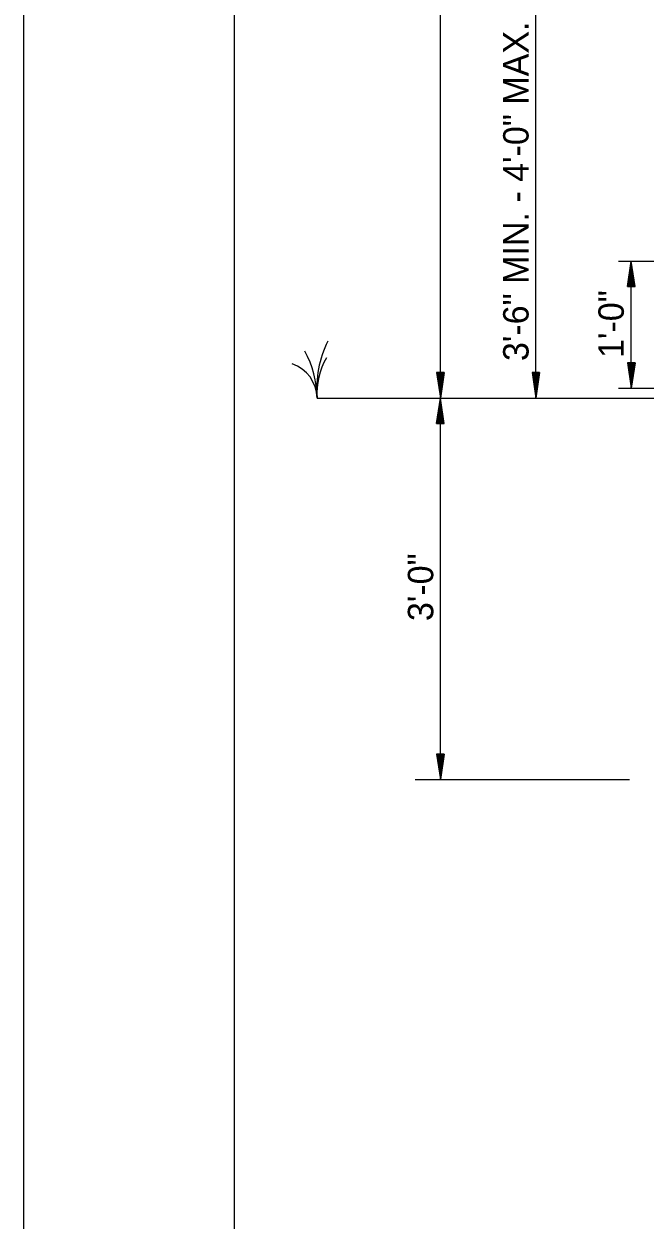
# Model space of a CAD drawing. Extents: x 1369885 to 1370886, y 379976 to 380616.
# Drawn here: x 1369885.5 to 1369995.4, y 380298 to 380509.6 of the extents above; entities that cross this region are included whole.
import ezdxf

# ---------------------------------------------------------------- set-up
doc = ezdxf.new("R2010")
doc.units = 0
for name, color, linetype in [('R_Border', 7, 'Continuous'), ('R_Draft', 7, 'Continuous'), ('R_No Plot', 7, 'Continuous')]:
    doc.layers.add(name, color=color, linetype=linetype)

msp = doc.modelspace()

# ---------------------------------------------------------------- linework, layer by layer
at = {"layer": 'R_Border'}
msp.add_line((1369922.71, 379987.52), (1369922.71, 380603.9), dxfattribs=at)
at = {"layer": 'R_Draft'}
for p, q in [((1369959.17, 380443.41), (1369959.17, 380582)), ((1369976.05, 380443.41), (1369976.05, 380533.41)), ((1369990.67, 380467.63), (1370003.78, 380467.63)), ((1369992.25, 380463.13), (1369992.92, 380467.63)), ((1369992.92, 380445.13), (1369992.92, 380467.63)), ((1369993.6, 380463.13), (1369992.92, 380467.63)), ((1369992.36, 380463.13), (1369992.92, 380466.88)), ((1369992.48, 380463.13), (1369992.92, 380466.1)), ((1369992.59, 380463.13), (1369992.92, 380465.35)), ((1369993.49, 380463.13), (1369992.92, 380466.88)), ((1369993.37, 380463.13), (1369992.92, 380466.1)), ((1369993.26, 380463.13), (1369992.92, 380465.35)), ((1369992.25, 380463.13), (1369993.6, 380463.13)), ((1369992.7, 380463.13), (1369992.92, 380464.59)), ((1369992.82, 380463.13), (1369992.92, 380463.84)), ((1369993.14, 380463.13), (1369992.92, 380464.59)), ((1369993.03, 380463.13), (1369992.92, 380463.84)), ((1369992.25, 380449.63), (1369992.92, 380445.13)), ((1369993.6, 380449.63), (1369992.25, 380449.63)), ((1369992.36, 380449.63), (1369992.92, 380445.88)), ((1369992.48, 380449.63), (1369992.92, 380446.65)), ((1369992.59, 380449.63), (1369992.92, 380447.4)), ((1369992.7, 380449.63), (1369992.92, 380448.17)), ((1369992.82, 380449.63), (1369992.92, 380448.92)), ((1369993.6, 380449.63), (1369992.92, 380445.13)), ((1369993.14, 380449.63), (1369992.92, 380448.17)), ((1369993.37, 380449.63), (1369992.92, 380446.65)), ((1369993.49, 380449.63), (1369992.92, 380445.88)), ((1369993.26, 380449.63), (1369992.92, 380447.4)), ((1369993.03, 380449.63), (1369992.92, 380448.92)), ((1369958.5, 380447.91), (1369959.17, 380443.41)), ((1369959.85, 380447.91), (1369958.5, 380447.91)), ((1369958.61, 380447.91), (1369959.17, 380444.16)), ((1369958.73, 380447.91), (1369959.17, 380444.93)), ((1369958.84, 380447.91), (1369959.17, 380445.68)), ((1369958.95, 380447.91), (1369959.17, 380446.44)), ((1369959.07, 380447.91), (1369959.17, 380447.2)), ((1369959.85, 380447.91), (1369959.17, 380443.41)), ((1369959.39, 380447.91), (1369959.17, 380446.44)), ((1369959.62, 380447.91), (1369959.17, 380444.93)), ((1369959.74, 380447.91), (1369959.17, 380444.16)), ((1369959.51, 380447.91), (1369959.17, 380445.68)), ((1369959.28, 380447.91), (1369959.17, 380447.2)), ((1369975.37, 380447.91), (1369976.05, 380443.41)), ((1369976.72, 380447.91), (1369975.37, 380447.91)), ((1369975.49, 380447.91), (1369976.05, 380444.16)), ((1369975.6, 380447.91), (1369976.05, 380444.93)), ((1369975.71, 380447.91), (1369976.05, 380445.68)), ((1369975.83, 380447.91), (1369976.05, 380446.44)), ((1369975.94, 380447.91), (1369976.05, 380447.2)), ((1369976.72, 380447.91), (1369976.05, 380443.41)), ((1369976.27, 380447.91), (1369976.05, 380446.44)), ((1369976.5, 380447.91), (1369976.05, 380444.93)), ((1369976.61, 380447.91), (1369976.05, 380444.16)), ((1369976.38, 380447.91), (1369976.05, 380445.68)), ((1369976.15, 380447.91), (1369976.05, 380447.2)), ((1369990.67, 380445.13), (1370003.78, 380445.13)), ((1369937.36, 380443.41), (1370175.16, 380443.41)), ((1369958.5, 380438.91), (1369959.17, 380443.41)), ((1369958.61, 380438.91), (1369959.17, 380442.66)), ((1369958.73, 380438.91), (1369959.17, 380441.88)), ((1369959.17, 380375.91), (1369959.17, 380443.41)), ((1369959.85, 380438.91), (1369959.17, 380443.41)), ((1369959.74, 380438.91), (1369959.17, 380442.66)), ((1369959.62, 380438.91), (1369959.17, 380441.88)), ((1369958.84, 380438.91), (1369959.17, 380441.13)), ((1369958.95, 380438.91), (1369959.17, 380440.37)), ((1369959.07, 380438.91), (1369959.17, 380439.62)), ((1369959.51, 380438.91), (1369959.17, 380441.13)), ((1369959.39, 380438.91), (1369959.17, 380440.37)), ((1369959.28, 380438.91), (1369959.17, 380439.62)), ((1369958.5, 380438.91), (1369959.85, 380438.91)), ((1369958.5, 380380.41), (1369959.17, 380375.91)), ((1369959.85, 380380.41), (1369958.5, 380380.41)), ((1369958.61, 380380.41), (1369959.17, 380376.66)), ((1369958.73, 380380.41), (1369959.17, 380377.43)), ((1369958.84, 380380.41), (1369959.17, 380378.18)), ((1369958.95, 380380.41), (1369959.17, 380378.94)), ((1369959.07, 380380.41), (1369959.17, 380379.7)), ((1369959.85, 380380.41), (1369959.17, 380375.91)), ((1369959.39, 380380.41), (1369959.17, 380378.94)), ((1369959.62, 380380.41), (1369959.17, 380377.43)), ((1369959.74, 380380.41), (1369959.17, 380376.66)), ((1369959.51, 380380.41), (1369959.17, 380378.18)), ((1369959.28, 380380.41), (1369959.17, 380379.7)), ((1369954.67, 380375.91), (1369992.64, 380375.91))]:
    msp.add_line(p, q, dxfattribs=at)
for centre, radius, start, end in [((1369956.23, 380445.06), 18.95, 153.6036, 185.017), ((1369920.15, 380443.29), 17.21, 0.407, 29.2294), ((1369949.3, 380444.38), 11.98, 149.1449, 184.6717), ((1369930.84, 380443.29), 6.52, 1.0116, 71.214)]:
    msp.add_arc(centre, radius, start, end, dxfattribs=at)
at = {"layer": 'R_No Plot'}
msp.add_lwpolyline([(1369885.49, 380615.59), (1370885.51, 380615.59), (1370885.51, 379975.58), (1369885.49, 379975.58)], close=True, dxfattribs=at)

# ---------------------------------------------------------------- texts
at = {"layer": 'R_Draft'}
for s, p in [('3\'-6" MIN. - 4\'-0" MAX.', (1369974.76, 380449.95)), ('1\'-0"', (1369991.61, 380450.5)), ('3\'-0"', (1369957.9, 380403.95))]:
    msp.add_text(s, height=4.5, rotation=90, dxfattribs=at).set_placement(p)

doc.saveas('drawing.dxf')
